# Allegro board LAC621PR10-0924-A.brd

Outline 306.3 x 113.1 mm; copper layers: TOP, GND1, IN1, GND2, IN2, IN3, VCC, IN4, GND3, BOTTOM. Coordinates in mm from the lower left corner of the outline.

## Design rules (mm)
net group 85H-SATA_3.9/5.3/4.3/4.3/5.3/3.9: nets SATA_LED SATA_LED#
net group CLK_ITPXDP-R: nets CLK_ITPXDP_N_R CLK_ITPXDP_P_R
net group CLK_PCIE_N1: nets CLK_PCIE_N1 CLK_PCIE_P1
net group CLK_PCIE_N2: nets CLK_PCIE_N2 CLK_PCIE_P2
net group CLK_PCIE_N3: nets CLK_PCIE_N3 CLK_PCIE_P3
net group CLK_PCIE_N4: nets CLK_PCIE_N4 CLK_PCIE_P4
net group CLK_PCIE_N5: nets CLK_PCIE_N5 CLK_PCIE_P5
net group CPU_DP1_N1: nets CPU_DP1_N1 CPU_DP1_P1
net group CPU_DP1_P0: nets CPU_DP1_N0 CPU_DP1_P0
net group CPU_DP1_P2: nets CPU_DP1_N2 CPU_DP1_P2
net group CPU_DP1_P3: nets CPU_DP1_N3 CPU_DP1_P3
net group CPU_DP2_N0: nets CPU_DP2_N0 CPU_DP2_P0
net group CPU_DP2_N0_C: nets CPU_DP2_N0_C CPU_DP2_P0_C
net group CPU_DP2_N1_C: nets CPU_DP2_N1_C CPU_DP2_P1_C
net group CPU_DP2_N2_C: nets CPU_DP2_N2_C CPU_DP2_P2_C
net group CPU_DP2_N3_C: nets CPU_DP2_N3_C CPU_DP2_P3_C
net group CPU_DP2_P1: nets CPU_DP2_N1 CPU_DP2_P1
net group CPU_DP2_P2: nets CPU_DP2_N2 CPU_DP2_P2
net group CPU_DP2_P3: nets CPU_DP2_N3 CPU_DP2_P3
net group CPU_DP3_AUXN: nets CPU_DP3_AUXN CPU_DP3_AUXP
net group CSS_1: nets CSSN_1 CSSP_1
net group CURRENT: nets DOCK_DCIN_IS+ DOCK_DCIN_IS-
net group DDRA-C-S10(11/10)/10(11/10)/19(20): nets DDR_A_CKE2 DDR_A_CKE3
net group DDRA-MA: nets DDR_A_MA7 DDR_A_MA10
net group DDRB-CTL: nets DDR_B_CKE2 DDR_B_CKE3
net group DIFFPAIR0: nets LPSS_UART2_RXD LPSS_UART2_TXD
net group DP2: nets SW1_DP0_AUXN_C SW1_DP0_AUXP_C
net group DP3_PCIE_PRX_C_DTX_11: nets PCIE_PRX_C_DTX_N11 PCIE_PRX_C_DTX_P11
net group DP3_PCIE_PRX_C_DTX_12: nets PCIE_PRX_C_DTX_N12 PCIE_PRX_C_DTX_P12
net group DP3_PCIE_PRX_C_RD_DTX_11: nets PCIE_PRX_C_RD_DTX_N11 PCIE_PRX_C_RD_DTX_P11
net group DP3_PCIE_PRX_C_RD_DTX_12: nets PCIE_PRX_C_RD_DTX_N12 PCIE_PRX_C_RD_DTX_P12
net group DP3_PCIE_PRX_DTX_11: nets PCIE_PRX_DTX_N11 PCIE_PRX_DTX_P11
net group DP3_PCIE_PRX_DTX_12: nets PCIE_PRX_DTX_N12 PCIE_PRX_DTX_P12
net group DP3_PCIE_PRX_RD_DTX_11: nets PCIE_PRX_RD_DTX_N11 PCIE_PRX_RD_DTX_P11
net group DP3_PCIE_PRX_RD_DTX_12: nets PCIE_PRX_RD_DTX_N12 PCIE_PRX_RD_DTX_P12
net group DP3_PCIE_PTX_C_DRX_11: nets PCIE_PTX_C_DRX_N11 PCIE_PTX_C_DRX_P11
net group DP3_PCIE_PTX_C_DRX_12: nets PCIE_PTX_C_DRX_N12 PCIE_PTX_C_DRX_P12
net group DP3_PCIE_PTX_C_RD_DRX_11: nets PCIE_PTX_C_RD_DRX_N11 PCIE_PTX_C_RD_DRX_P11
net group DP3_PCIE_PTX_C_RD_DRX_12: nets PCIE_PTX_C_RD_DRX_N12 PCIE_PTX_C_RD_DRX_P12
net group DP3_PCIE_PTX_DRX_11: nets PCIE_PTX_DRX_N11 PCIE_PTX_DRX_P11
net group DP3_PCIE_PTX_DRX_12: nets PCIE_PTX_DRX_N12 PCIE_PTX_DRX_P12
net group DP3_PCIE_PTX_RD_DRX_11: nets PCIE_PTX_RD_DRX_N11 PCIE_PTX_RD_DRX_P11
net group DP3_PCIE_PTX_RD_DRX_12: nets PCIE_PTX_RD_DRX_N12 PCIE_PTX_RD_DRX_P12
net group DP3_SATA_PRX_C_DTX_0: nets SATA_PRX_C_DTX_N0 SATA_PRX_C_DTX_P0
net group DP3_SATA_PRX_C_RD_DTX_0: nets SATA_PRX_C_RD_DTX_N0 SATA_PRX_C_RD_DTX_P0
net group DP3_SATA_PRX_DTX_0: nets SATA_PRX_DTX_N0 SATA_PRX_DTX_P0
net group DP3_SATA_PRX_RD_DTX_0: nets SATA_PRX_RD_DTX_N0 SATA_PRX_RD_DTX_P0
net group DP3_SATA_PTX_C_DRX_0: nets SATA_PTX_C_DRX_N0 SATA_PTX_C_DRX_P0
net group DP3_SATA_PTX_C_RD_DRX_0: nets SATA_PTX_C_RD_DRX_N0 SATA_PTX_C_RD_DRX_P0
net group DP3_SATA_PTX_DRX_0: nets SATA_PTX_DRX_N0 SATA_PTX_DRX_P0
net group DP3_SATA_PTX_RD_DRX_0: nets SATA_PTX_RD_DRX_N0 SATA_PTX_RD_DRX_P0
net group DP3_USB20_2_R: nets USB20_N2_R USB20_P2_R
net group DP4: nets VCC_GT_SENSE VSS_GT_SENSE
net group DP5: nets VCCIO_SENSE VSSIO_SENSE
net group DP6: nets VCCSENSE VSSSENSE
net group DP_HUB-DP0-0: nets HUB_DP0_N0 HUB_DP0_P0
net group DP_HUB-DP0-0-C: nets HUB_DP0_N0_C HUB_DP0_P0_C
net group DP_HUB-DP0-0-R: nets HUB_DP0_N0_R HUB_DP0_P0_R
net group DP_HUB-DP0-1: nets HUB_DP0_N1 HUB_DP0_P1
net group DP_HUB-DP0-1-C: nets HUB_DP0_N1_C HUB_DP0_P1_C
net group DP_HUB-DP0-1-R: nets HUB_DP0_N1_R HUB_DP0_P1_R
net group DP_HUB-DP0-2: nets HUB_DP0_N2 HUB_DP0_P2
net group DP_HUB-DP0-2-C: nets HUB_DP0_N2_C HUB_DP0_P2_C
net group DP_HUB-DP0-2-R: nets HUB_DP0_N2_R HUB_DP0_P2_R
net group DP_HUB-DP0-3: nets HUB_DP0_N3 HUB_DP0_P3
net group DP_HUB-DP0-3-C: nets HUB_DP0_N3_C HUB_DP0_P3_C
net group DP_HUB-DP0-3-R: nets HUB_DP0_N3_R HUB_DP0_P3_R
net group DP_HUB-DP1-0: nets HUB_DP1_N0 HUB_DP1_P0
net group DP_HUB-DP1-0-C: nets HUB_DP1_N0_C HUB_DP1_P0_C
net group DP_HUB-DP1-0-R: nets HUB_DP1_N0_R HUB_DP1_P0_R
net group DP_HUB-DP1-1: nets HUB_DP1_N1 HUB_DP1_P1
net group DP_HUB-DP1-1-C: nets HUB_DP1_N1_C HUB_DP1_P1_C
net group DP_HUB-DP1-1-R: nets HUB_DP1_N1_R HUB_DP1_P1_R
net group DP_HUB-DP1-2: nets HUB_DP1_N2 HUB_DP1_P2
net group DP_HUB-DP1-2-C: nets HUB_DP1_N2_C HUB_DP1_P2_C
net group DP_HUB-DP1-2-R: nets HUB_DP1_N2_R HUB_DP1_P2_R
net group DP_HUB-DP1-3: nets HUB_DP1_N3 HUB_DP1_P3
net group DP_HUB-DP1-3-C: nets HUB_DP1_N3_C HUB_DP1_P3_C
net group DP_HUB-DP1-3-R: nets HUB_DP1_N3_R HUB_DP1_P3_R
net group DP_SW1-DP1-0: nets SW1_DP1_N0 SW1_DP1_P0
net group DP_SW1-DP1-0-C: nets SW1_DP1_N0_C SW1_DP1_P0_C
net group DP_SW1-DP1-1: nets SW1_DP1_N1 SW1_DP1_P1
net group DP_SW1-DP1-1-C: nets SW1_DP1_N1_C SW1_DP1_P1_C
net group DP_SW1-DP1-2: nets SW1_DP1_N2 SW1_DP1_P2
net group DP_SW1-DP1-2-C: nets SW1_DP1_N2_C SW1_DP1_P2_C
net group DP_SW1-DP1-3: nets SW1_DP1_N3 SW1_DP1_P3
net group DP_SW1-DP1-3-C: nets SW1_DP1_N3_C SW1_DP1_P3_C
net group DP_SW1_DP0_0: nets SW1_DP0_N0 SW1_DP0_P0
net group DP_SW1_DP0_0_C: nets SW1_DP0_N0_C SW1_DP0_P0_C
net group DP_SW1_DP0_1: nets SW1_DP0_N1 SW1_DP0_P1
net group DP_SW1_DP0_1_C: nets SW1_DP0_N1_C SW1_DP0_P1_C
net group DP_SW1_DP0_2: nets SW1_DP0_N2 SW1_DP0_P2
net group DP_SW1_DP0_2_C: nets SW1_DP0_N2_C SW1_DP0_P2_C
net group DP_SW1_DP0_3: nets SW1_DP0_N3 SW1_DP0_P3
net group DP_SW1_DP0_3_C: nets SW1_DP0_N3_C SW1_DP0_P3_C
net group HUB_DP0_AUX-C: nets HUB_DP0_AUXN_C HUB_DP0_AUXP_C
net group HUB_DP1_AUX-C: nets HUB_DP1_AUXN_C HUB_DP1_AUXP_C
net group PCIE_PRX_C_DTX_N9: nets PCIE_PRX_C_DTX_N9 PCIE_PRX_C_DTX_P9
net group PCIE_PRX_C_DTX_N10: nets PCIE_PRX_C_DTX_N10 PCIE_PRX_C_DTX_P10
net group PCIE_PRX_DTX_N5: nets PCIE_PRX_DTX_N5 PCIE_PRX_DTX_P5
net group PCIE_PRX_DTX_N6: nets PCIE_PRX_DTX_N6 PCIE_PRX_DTX_P6
net group PCIE_PRX_DTX_N9: nets PCIE_PRX_DTX_N9 PCIE_PRX_DTX_P9
net group PCIE_PRX_DTX_N10: nets PCIE_PRX_DTX_N10 PCIE_PRX_DTX_P10
net group PCIE_PTX_C_DRX_N5: nets PCIE_PTX_C_DRX_N5 PCIE_PTX_C_DRX_P5
net group PCIE_PTX_C_DRX_N6: nets PCIE_PTX_C_DRX_N6 PCIE_PTX_C_DRX_P6
net group PCIE_PTX_C_DRX_N9: nets PCIE_PTX_C_DRX_N9 PCIE_PTX_C_DRX_P9
net group PCIE_PTX_C_DRX_N10: nets PCIE_PTX_C_DRX_N10 PCIE_PTX_C_DRX_P10
net group PCIE_PTX_DRX_N5: nets PCIE_PTX_DRX_N5 PCIE_PTX_DRX_P5
net group PCIE_PTX_DRX_N6: nets PCIE_PTX_DRX_N6 PCIE_PTX_DRX_P6
net group PCIE_PTX_DRX_N9: nets PCIE_PTX_DRX_N9 PCIE_PTX_DRX_P9
net group PCIE_PTX_DRX_N10: nets PCIE_PTX_DRX_N10 PCIE_PTX_DRX_P10
net group PECI-SINGLE: nets PECI_EC PECI_EC_R
net group REM_DIODE1_: nets REM_DIODE1_N REM_DIODE1_P
net group REM_DIODE2_: nets REM_DIODE2_N REM_DIODE2_P
net group REM_DIODE4_: nets REM_DIODE4_N REM_DIODE4_P
net group RJ45_MDIN0: nets RJ45_MDIN0 RJ45_MDIP0
net group RJ45_MDIN1: nets RJ45_MDIN1 RJ45_MDIP1
net group RJ45_MDIN2: nets RJ45_MDIN2 RJ45_MDIP2
net group RJ45_MDIN3: nets RJ45_MDIN3 RJ45_MDIP3
net group SATA_PRX_C_DTX_N1: nets SATA_PRX_C_DTX_N1 SATA_PRX_C_DTX_P1
net group SATA_PRX_DTX_N1: nets SATA_PRX_DTX_N1 SATA_PRX_DTX_P1
net group SATA_PTX_C_DRX_N1: nets SATA_PTX_C_DRX_N1 SATA_PTX_C_DRX_P1
net group SATA_PTX_DRX_N1: nets SATA_PTX_DRX_N1 SATA_PTX_DRX_P1
net group SD/MMCDAT0/RCLK+: nets SD/MMCDAT0/RCLK+ SD/MMCDAT1/RCLK-
net group SD/MMCDAT-RCLKR: nets SD/MMCDAT0/RCLK+_R SD/MMCDAT1/RCLK-_R
net group SW1_DP1_AUX-C: nets SW1_DP1_AUXN_C SW1_DP1_AUXP_C
net group USB3_PRX_DTX_N3: nets USB3_PRX_DTX_N3 USB3_PRX_DTX_P3
net group USB3_PRX_DTX_N4: nets USB3_PRX_DTX_N4 USB3_PRX_DTX_P4
net group USB3_PRX_DTX_P1: nets USB3_PRX_DTX_N1 USB3_PRX_DTX_P1
net group USB3_PRX_DTX_P2: nets USB3_PRX_DTX_N2 USB3_PRX_DTX_P2
net group USB3_PRX_L_DTX_N1: nets USB3_PRX_L_DTX_N1 USB3_PRX_L_DTX_P1
net group USB3_PRX_L_DTX_N3: nets USB3_PRX_L_DTX_N3 USB3_PRX_L_DTX_P3
net group USB3_PTX_C_DRX_N1: nets USB3_PTX_C_DRX_N1 USB3_PTX_C_DRX_P1
net group USB3_PTX_C_DRX_N3: nets USB3_PTX_C_DRX_N3 USB3_PTX_C_DRX_P3
net group USB3_PTX_DRX_N1: nets USB3_PTX_DRX_N1 USB3_PTX_DRX_P1
net group USB3_PTX_DRX_N2: nets USB3_PTX_DRX_N2 USB3_PTX_DRX_P2
net group USB3_PTX_DRX_N3: nets USB3_PTX_DRX_N3 USB3_PTX_DRX_P3
net group USB3_PTX_DRX_N4: nets USB3_PTX_DRX_N4 USB3_PTX_DRX_P4
net group USB3_PTX_L_DRX_N1: nets USB3_PTX_L_DRX_N1 USB3_PTX_L_DRX_P1
net group USB3_PTX_L_DRX_N3: nets USB3_PTX_L_DRX_N3 USB3_PTX_L_DRX_P3
net group VSA_SEN: nets VSA_SEN+ VSA_SEN-
net group ASYNCHRONOUS: nets +DDR_VREF_A_CA +DDR_VREF_B_DQ CFG_RCOMP CPU_POPIRCOMP DDR_DRAMRST# DDR_DRAMRST#_R EDP_COMP EDRAM_OPIO_RCOMP EMMC_RCOMP EOPIO_RCOMP H_CATERR# H_PROCHOT# H_PROCHOT#_R H_PROCHOT#_R1 H_THERMTRIP# PCH_PLTRST# PCH_PLTRST#_EC PCH_POPIRCOMP PCIE_RCOMPN PCIE_RCOMPP PLTRST_5048# PLTRST_LAN# PLTRST_TPM# PLTRST_VMM2320# SD_RCOMP SM_RCOMP0 SM_RCOMP1 SM_RCOMP2 THERMATRIP2# THERMATRIP3# USBCOMP VCCST_PWRGD XDP_OBS0 XDP_OBS0_R XDP_OBS1 XDP_OBS1_R XDP_OBS2_R XDP_OBS3_R
net group BC: nets BC_CLK_ECE1117 BC_CLK_ECE5048 BC_DAT_ECE1117 BC_DAT_ECE5048
net group CARD READER: nets SD/MMCCD# SD/MMCCLK SD/MMCCLK_R SD/MMCCMD SD/MMCDAT2 SD/MMCDAT2_R SD/MMCDAT3 SD/MMCDAT3_R SDWP
net group CL_IAMT: nets PCH_CL_CLK1 PCH_CL_DATA1 PCH_CL_RST1#
net group CLK: nets CLK_27M_IN CLK_27M_OUT CLK_27M_OUT_R CLK_PCI_DOCK CLK_PCI_LPDEBUG CLK_PCI_MEC CLKDET# CLKREQ_PCIE#0 CLKREQ_PCIE#1 CLKREQ_PCIE#2 CLKREQ_PCIE#3 CLKREQ_PCIE#4 CLKREQ_PCIE#5 CPU_XDP_TCLK DAI_12MHZ# DAI_BCLK# DMIC_CLK0 DMIC_CLK_CODEC HDA_BIT_CLK HDA_BIT_CLK_R HUB_SPI_CLK I2S_MCLK JTAG_CLK MEC_XTAL1 MEC_XTAL2 MEC_XTAL2_R MSCLK PCH_JTAG_TCK PCI_CLK_LPC0 PCI_CLK_LPC1 XCLK_BIASREF XTAL24_IN XTAL24_OUT XTAL24_OUT_R XTALI XTALO XTALO_R
net group CLK-DF: nets CLK_ITPXDP_N CLK_ITPXDP_P CLK_PCIE_N0 CLK_PCIE_P0
net group CODEC: nets AUD_HP_NB_SENSE AUD_SENSE_A AUD_SENSE_B RING2 RING2_R SLEEVE SLEEVE_R
net group CRITICAL: nets H_VCCST_PWRGD_XDP INTRUDER# PCH_DPWROK PCH_PCIE_WAKE# PCH_RSMRST# PCH_RSMRST#_Q PCIE_WAKE# PCIE_WAKE#_R RESET_OUT# RESET_OUT#_R SIO_PWRBTN# SIO_RCIN#
net group CRITICAL SIGNALS: nets H_CPUPWRGD SIO_SLP_A# XDP_DBRESET#
net group CRT: nets HUB_VGA_BLUE HUB_VGA_GREEN HUB_VGA_HSYNC HUB_VGA_RED HUB_VGA_VSYNC SW2_VGA1_BLUE SW2_VGA1_GREEN SW2_VGA1_HSYNC SW2_VGA1_RED SW2_VGA1_VSYNC SW2_VGA2_BLUE SW2_VGA2_GREEN SW2_VGA2_HSYNC SW2_VGA2_RED SW2_VGA2_VSYNC VGA1_BLUE_L VGA1_GREEN_L VGA1_HSYNC_L VGA1_RED_L VGA1_VSYNC_L
net group DDR: nets DDR_A_CKE0 DDR_A_CKE1 DDR_A_CLK0 DDR_A_CLK1 DDR_A_CLK#0 DDR_A_CLK#1 DDR_A_CS#0 DDR_A_CS#1 DDR_A_D0 DDR_A_D1 DDR_A_D2 DDR_A_D3 DDR_A_D4 DDR_A_D5 DDR_A_D6 DDR_A_D7 DDR_A_D8 DDR_A_D9 DDR_A_D10 DDR_A_D11 DDR_A_D12 DDR_A_D13 DDR_A_D14 DDR_A_D15 DDR_A_D16 DDR_A_D17 DDR_A_D18 DDR_A_D19 DDR_A_D20 DDR_A_D21 DDR_A_D22 DDR_A_D23 DDR_A_D24 DDR_A_D25 DDR_A_D26 DDR_A_D27 DDR_A_D28 DDR_A_D29 DDR_A_D30 DDR_A_D31 DDR_A_D32 DDR_A_D33 DDR_A_D34 DDR_A_D35 DDR_A_D36 DDR_A_D37 DDR_A_D38 DDR_A_D39 DDR_A_D40 DDR_A_D41 DDR_A_D42 DDR_A_D43 DDR_A_D44 DDR_A_D45 DDR_A_D46 DDR_A_D47 DDR_A_D48 DDR_A_D49 DDR_A_D50 DDR_A_D51 DDR_A_D52 DDR_A_D53 DDR_A_D54 DDR_A_D55 DDR_A_D56 DDR_A_D57 DDR_A_D58 DDR_A_D59 DDR_A_D60 DDR_A_D61 DDR_A_D62 DDR_A_D63 DDR_A_DQS0 DDR_A_DQS1 DDR_A_DQS2 DDR_A_DQS3 DDR_A_DQS4 DDR_A_DQS5 DDR_A_DQS6 DDR_A_DQS7 DDR_A_DQS#0 DDR_A_DQS#1 DDR_A_DQS#2 DDR_A_DQS#3 DDR_A_DQS#4 DDR_A_DQS#5 DDR_A_DQS#6 DDR_A_DQS#7 DDR_A_MA0 DDR_A_MA1 DDR_A_MA2 DDR_A_MA3 DDR_A_MA4 DDR_A_MA5 DDR_A_MA6 DDR_A_MA8 DDR_A_MA9 DDR_A_MA11 DDR_A_MA12 DDR_A_MA13 DDR_A_MA14 DDR_A_MA15 DDR_A_ODT0 DDR_A_ODT1 DDR_B_CKE0 DDR_B_CKE1 DDR_B_CLK0 DDR_B_CLK1 DDR_B_CLK#0 DDR_B_CLK#1 DDR_B_CS#0 DDR_B_CS#1 DDR_B_D0 DDR_B_D1 DDR_B_D2 DDR_B_D3 DDR_B_D4 DDR_B_D5 DDR_B_D6 DDR_B_D7 DDR_B_D8 DDR_B_D9 DDR_B_D10 DDR_B_D11 DDR_B_D12 DDR_B_D13 DDR_B_D14 DDR_B_D15 DDR_B_D16 DDR_B_D17 DDR_B_D18 DDR_B_D19 DDR_B_D20 DDR_B_D21 DDR_B_D22 DDR_B_D23 DDR_B_D24 DDR_B_D25 DDR_B_D26 DDR_B_D27 DDR_B_D28 DDR_B_D29 DDR_B_D30 DDR_B_D31 DDR_B_D32 DDR_B_D33 DDR_B_D34 DDR_B_D35 DDR_B_D36 DDR_B_D37 DDR_B_D38 DDR_B_D39 DDR_B_D40 DDR_B_D41 DDR_B_D42 DDR_B_D43 DDR_B_D44 DDR_B_D45 DDR_B_D46 DDR_B_D47 DDR_B_D48 DDR_B_D49 DDR_B_D50 DDR_B_D51 DDR_B_D52 DDR_B_D53 DDR_B_D54 DDR_B_D55 DDR_B_D56 DDR_B_D57 DDR_B_D58 DDR_B_D59 DDR_B_D60 DDR_B_D61 DDR_B_D62 DDR_B_D63 DDR_B_DQS0 DDR_B_DQS1 DDR_B_DQS2 DDR_B_DQS3 DDR_B_DQS4 DDR_B_DQS5 DDR_B_DQS6 DDR_B_DQS7 DDR_B_DQS#0 DDR_B_DQS#1 DDR_B_DQS#2 DDR_B_DQS#3 DDR_B_DQS#4 DDR_B_DQS#5 DDR_B_DQS#6 DDR_B_DQS#7 DDR_B_MA0 DDR_B_MA1 DDR_B_MA2 DDR_B_MA3 DDR_B_MA4 DDR_B_MA5 DDR_B_MA6 DDR_B_MA7 DDR_B_MA8 DDR_B_MA9 DDR_B_MA10 DDR_B_MA11 DDR_B_MA13 DDR_B_MA14 DDR_B_MA15 DDR_B_ODT0 DDR_B_ODT1
net group DDRA-MA-S10(11/10)/10(11/10)/19(20): nets DDR_A_ACT# DDR_A_BA0 DDR_A_BA1 DDR_A_BG0 DDR_A_BG1 DDR_A_MA16 DDR_A_PARITY
net group DDRB-MA: nets DDR_B_MA12
net group DDRB-MA-S10(11/10)/10(11/10)/19(20): nets DDR_B_ACT# DDR_B_BA0 DDR_B_BA1 DDR_B_BG0 DDR_B_BG1 DDR_B_MA16 DDR_B_PARITY
net group DP: nets CPU_DP2_AUXN CPU_DP2_AUXN_C CPU_DP2_AUXP CPU_DP2_AUXP_C HUB_DP0_AUXN HUB_DP0_AUXP HUB_DP1_AUXN HUB_DP1_AUXP HUB_DP1_SCL HUB_DP1_SDA HUB_SW1_AUXN HUB_SW1_AUXP HUB_SW2_AUXN HUB_SW2_AUXP SW1_DP0_AUXN SW1_DP0_AUXP SW1_DP1_AUXN SW1_DP1_AUXP
net group DP_3.9/3.7/4.3/4.3/3.7/3.9: nets CPU_DP2_HPD
net group EDP: nets EDP_AUXN EDP_AUXN_C EDP_AUXP EDP_AUXP_C EDP_TXN0 EDP_TXN0_C EDP_TXN1 EDP_TXN1_C EDP_TXP0 EDP_TXP0_C EDP_TXP1 EDP_TXP1_C
net group EMI: nets BIA_PWM BIA_PWM_EC BST_3V BST_5V CLKRUN# DAI_LRCK# EC5048_TX EDP_BIA_PWM HOST_DEBUG_TX I2S_BCLK M_ID2# TP_LAN_JTAG_TCK
net group ESD-GND: nets CPU_XDP_PRDY# CPU_XDP_PREQ# CPU_XDP_TDI CPU_XDP_TDO CPU_XDP_TMS CPU_XDP_TRST# PCH_JTAG_TDI PCH_JTAG_TDO PCH_JTAG_TMS POWER_SW#_MB POWER_SW_IN# RUNPWROK
net group ESD-NOCROSS-MOAT: nets CFG0 CFG1 CFG2 CFG3 CFG4 CFG5 CFG6 CFG7 CFG8 CFG9 CFG10 CFG11 CFG12 CFG13 CFG14 CFG15 CFG16 CFG17 CFG18 CFG19 SIO_EXT_SMI#
net group HDA: nets HDA_RST# HDA_RST#_R HDA_SDIN0 HDA_SDIN0_R HDA_SDOUT HDA_SDOUT_R HDA_SYNC HDA_SYNC_R
net group HDMI: nets CPU_DP1_AUXN CPU_DP1_AUXP HDMI_CLKN HDMI_CLKP HDMI_L_CLKN HDMI_L_CLKP HDMI_L_TX_N0 HDMI_L_TX_N1 HDMI_L_TX_N2 HDMI_L_TX_P0 HDMI_L_TX_P1 HDMI_L_TX_P2 HDMI_TX_N0 HDMI_TX_N1 HDMI_TX_N2 HDMI_TX_P0 HDMI_TX_P1 HDMI_TX_P2
net group HP: nets AUD_HP_OUT_L AUD_HP_OUT_L1 AUD_HP_OUT_R AUD_HP_OUT_R1 AUD_OUT_L AUD_OUT_R
net group I2C: nets I2C_1_SCL I2C_1_SDA I2C_HUB_SCL I2C_HUB_SDA ISH_I2C2_SCL ISH_I2C2_SCL_R ISH_I2C2_SDA ISH_I2C2_SDA_R
net group MDI: nets LAN_MDIN0 LAN_MDIN0_L LAN_MDIN1 LAN_MDIN1_L LAN_MDIN2 LAN_MDIN2_L LAN_MDIN3 LAN_MDIN3_L LAN_MDIP0 LAN_MDIP0_L LAN_MDIP1 LAN_MDIP1_L LAN_MDIP2 LAN_MDIP2_L LAN_MDIP3 LAN_MDIP3_L SW_LAN0_MDIN0 SW_LAN0_MDIN1 SW_LAN0_MDIN2 SW_LAN0_MDIN3 SW_LAN0_MDIP0 SW_LAN0_MDIP1 SW_LAN0_MDIP2 SW_LAN0_MDIP3 SW_LAN1_MDIN0 SW_LAN1_MDIN1 SW_LAN1_MDIN2 SW_LAN1_MDIN3 SW_LAN1_MDIP0 SW_LAN1_MDIP1 SW_LAN1_MDIP2 SW_LAN1_MDIP3
net group OTHER-SINGLE: nets BAT1_LED# BAT2_LED# BATT_WHITE# BATT_YELLOW#
net group PCIE: nets PCIE_PRX_DTX_N3 PCIE_PRX_DTX_P3 PCIE_PTX_C_DRX_N3 PCIE_PTX_C_DRX_P3 PCIE_PTX_DRX_N3 PCIE_PTX_DRX_P3
net group POWER-20: nets +1.0V_PRIM_COREP +1.0V_VCCST_C +1.0V_VCCSTG_C +1.0V_VCCSTG_R +1.5V_VIN +1.8VALWP +1VALWP +1VALWP_B+ +1VS_VCCIOP +3.3V_RUN_AUDIO_UZ5 +DV33_18 +REGCTL_PNP10 +SDREG2 +SIM_PWR CHAGER_SRC GPU_B+
net group POWERS: nets +1.0V_AMPHYPLL +1.0V_APLLEBB +1.0V_CLK1 +1.0V_CLK2 +1.0V_CLK3 +1.0V_CLK4 +1.0V_CLK5 +1.0V_CLK6 +1.0V_DTS +1.0V_MPHYAON +1.0V_PRIM_CORE +1.0V_PRIM_XDP +1.0V_RUN_VMM +1.0V_SRAM +1.0V_VCCST +1.0V_VCCSTG +1.0V_VMM_VDD +1.0V_VMM_VDDTX +1.0VO_DSW +1.0VS_VCCIO +1.5V_RUN +1.5V_RUN_AUDIO +3.3V_1.8V_PGPPA +3.3V_1.8V_PGPPG +3.3V_ALW_DSW +3.3V_LAN_UZ2 +3.3V_M_TPM +3.3V_M_UZ8 +3.3V_MMI_AUX +3.3V_MMI_IN +3.3V_PGPPD +3.3V_PGPPE +3.3V_RUN_UZ3 +3.3V_WLAN_UZ3 +3.3V_WWAN +5V_RUN_PVDD +EDP_VDD +USB_REAR_PWR +VCC_GTUS
net group PWR: nets +0.9V_LAN +1.2V_LDO +1.8V_RUN_CARD +3.3V_ALW2 +3.3V_ALW_PCH +3.3V_ALW_UE1 +3.3V_ALW_UE2 +3.3V_ALWP +3.3V_CAM +3.3V_HDD +3.3V_LAN +3.3V_LAN_OUT +3.3V_M +3.3V_RTC_LDO +3.3V_RUN_AUDIO +3.3V_RUN_CARD +3.3V_RUN_VDDA +3.3V_RUN_VDDIO +3.3V_RUN_VMM +3.3V_SPI +3.3V_TP +3.3V_WLAN +5V_ALW2 +5V_ALWP +5V_HDD +5V_RUN +5V_RUN_AUDIO +5V_USB_CHG_PWR +BL_PWR_SRC +CAP_LDO +COINCELL +CRT_VCC +DC_IN +DC_IN_SS +DCIN +DCIN_JACK +GND_CHASSIS +LCDVDD +LOM_VCT +MIC1_VREF_OUT +NBDOCK_DC_IN_SS +PBATT +PECI_VREF +RSVD_VCC3P3_1 +RTC_CELL +RTC_CELL_VBAT +SDC_IN +USB_LEFT_PWR +V_DDR_REF +VCHGR +VDDA_AVDD1 +VDDA_PVDD +VHDMI_VCC +VR_CAP +VREFOUT
net group RTC: nets PCH_RTCRST# PCH_RTCX1 PCH_RTCX2 PCH_RTCX2_R SRTCRST# SUSCLK SUSCLK_R WIGIG_32KHZ
net group S-20/20: nets +DDR_VREF_CA
net group SD: nets SD_UHS2_D0N SD_UHS2_D0P SD_UHS2_D1N SD_UHS2_D1P
net group SD-NOCROSS-MOAT: nets DOCK_POR_RST# JTAG_RST# ME_SUS_PWR_ACK SUSACK# USB_OC0# USB_OC1# USB_OC2#
net group SIM: nets UIM_CLK UIM_DATA UIM_RESET
net group SM: nets CHARGER_SMBCLK CHARGER_SMBDAT CLK_KBD CLK_MSE CLK_TP_SIO CPU_DP1_CTRL_CLK CPU_DP1_CTRL_DATA CPU_DP2_CTRL_CLK CPU_DP2_CTRL_DATA DAT_KBD DAT_MSE DAT_TP_SIO DDR_XDP_WAN_SMBCLK DDR_XDP_WAN_SMBDAT DOCK_SMB_CLK DOCK_SMB_DAT HUB_DP0_SCL HUB_DP0_SDA HUB_VGA_SCL HUB_VGA_SDA MEM_SMBCLK MEM_SMBDATA PBAT_SMBCLK PBAT_SMBCLK_C PBAT_SMBDAT PBAT_SMBDAT_C SML0_SMBCLK SML0_SMBDATA SML1_SMBCLK SML1_SMBDATA SW2_VGA1_SCL SW2_VGA1_SDA SW2_VGA2_SCL SW2_VGA2_SDA USH_SMBCLK USH_SMBDAT
net group SMB: nets GPU_SMBCLK
net group SMB-5: nets GPU_SMBDAT
net group SPI: nets CLK_PCI_5048 PCH_SPI_CLK PCH_SPI_CLK_0_R PCH_SPI_CLK_1_R PCH_SPI_CLK_2_R PCH_SPI_CLK_R1 PCH_SPI_CS#0 PCH_SPI_CS#0_R1 PCH_SPI_CS#0_R2 PCH_SPI_CS#1 PCH_SPI_CS#1_R1 PCH_SPI_CS#1_R2 PCH_SPI_CS#2 PCH_SPI_CS#2_R PCH_SPI_D0 PCH_SPI_D0_0_R PCH_SPI_D0_1_R PCH_SPI_D0_2_R PCH_SPI_D0_R1 PCH_SPI_D1 PCH_SPI_D1_0_R PCH_SPI_D1_1_R PCH_SPI_D1_2_R PCH_SPI_D1_R1 PCH_SPI_D2 PCH_SPI_D2_0_R PCH_SPI_D2_1_R PCH_SPI_D2_R1 PCH_SPI_D3 PCH_SPI_D3_0_R PCH_SPI_D3_1_R PCH_SPI_D3_R1 PCH_SPI_DO2_XDP PCH_SPI_DO_XDP
net group SPK: nets INT_SPK_L+ INT_SPK_L- INT_SPK_R+ INT_SPK_R- INT_SPKR_L+ INT_SPKR_L- INT_SPKR_R+ INT_SPKR_R-
net group SVID: nets H_CPU_SVIDALRT# VIDALERT_N VIDSCLK VIDSOUT
net group USB2.0: nets USB20_N4_R USB20_N9_R USB20_P4_R USB20_P9_R
net group USB3.0: nets USB3_PRX_DTX_N5 USB3_PRX_DTX_P5 USB3_PRX_L_DTX_N4 USB3_PRX_L_DTX_P4 USB3_PTX_C_DRX_N4 USB3_PTX_C_DRX_P4 USB3_PTX_DRX_N5 USB3_PTX_DRX_P5 USB3_PTX_L_DRX_N4 USB3_PTX_L_DRX_P4
net group USB3.0-DF12/12: nets USB3_PRX_L_DTX_N5 USB3_PRX_L_DTX_P5 USB3_PTX_C_DRX_N5 USB3_PTX_C_DRX_P5 USB3_PTX_L_DRX_N5 USB3_PTX_L_DRX_P5
net group USB20: nets SW_USB20_N1 SW_USB20_P1 USB20_N1 USB20_N1_R USB20_N2 USB20_N3 USB20_N3_R USB20_N4 USB20_N5 USB20_N6 USB20_N7 USB20_N8 USB20_N9 USB20_N10 USB20_P1 USB20_P1_R USB20_P2 USB20_P3 USB20_P3_R USB20_P4 USB20_P5 USB20_P6 USB20_P7 USB20_P8 USB20_P9 USB20_P10

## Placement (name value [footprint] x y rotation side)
C33  -  [C_0805]  131.53 95.75 270 bottom
C42  -  [C_0402]  156.04 108.11 270 top
C43  -  [C_0402]  154.27 107.19 90 top
C263  -  [C_0402]  285.42 83.74 180 bottom
C294  -  [C_0402]  135.98 106.81 90 top
C295  -  [C_0402]  138.26 93.76 270 bottom
C296  -  [C_0402]  136.87 106.81 90 top
C297  -  [C_0402]  139.28 93.76 270 bottom
C298  -  [C_0402]  137.76 106.81 90 top
C299  -  [C_0402]  140.17 93.76 270 bottom
C300  -  [C_0402]  143.09 93.76 270 bottom
C301  -  [C_0402]  143.98 93.76 270 bottom
C302  -  [C_0402]  137.37 93.76 270 bottom
C303  -  [C_0402]  138.64 106.81 90 top
C304  -  [C_0402]  141.18 93.76 270 bottom
C305  -  [C_0402]  139.53 106.81 90 top
C306  -  [C_0402]  142.07 93.76 270 bottom
C307  -  [C_0402]  140.42 106.81 90 top
C308  -  [C_0402]  141.31 106.81 90 top
C309  -  [C_0402]  142.2 106.81 90 top
C310  -  [C_0402]  146.54 95.89 270 bottom
C311  -  [C_0402]  143.5 109.38 0 top
C312  -  [C_0402]  148.68 102.9 90 top
C313  -  [C_0402]  149.57 102.9 90 top
C314  -  [C_0402]  150.46 103.81 270 top
C315  -  [C_0402]  151.34 103.81 270 top
C316  -  [C_0402]  164.98 109.43 0 top
C317  -  [C_0603]  130.06 95.83 270 bottom
C318  -  [C_0603]  179.03 101.81 270 top
C319  -  [C_0402]  165.11 101.04 0 top
CA1  -  [C_0402]  291.43 34.88 270 top
CA2  -  [C_0402]  290.84 36.91 0 top
CA3  -  [C_0402]  290.84 38.43 0 top
CA4  -  [C_0402]  291.96 32.27 270 top
CA5  -  [C_0402]  93.1 86.92 270 top
CA6  -  [C_0402]  93.99 86.92 270 top
CA7  -  [C_0201]  91.89 86.35 270 top
CA8  -  [C_0201]  284.91 31.7 0 top
CA9  -  [C_0603]  284.3 30.81 0 top
CA10  -  [C_0603]  273.8 33.99 180 top
CA11  -  [C_0201]  274.4 31.1 270 top
CA12  -  [C_0402]  294.7 35.61 0 top
CA13  -  [C_0402]  295.62 34.24 180 top
CA16  -  [C_0603]  283.93 39.07 90 top
CA17  -  [C_0201]  286.82 38.94 0 top
CA18  -  [C_0603]  286.41 39.83 0 top
CA19  -  [C_0402]  277.3 39.63 90 top
CA22  -  [C_0402]  279.97 39.65 90 top
CA23  -  [C_0402]  279.08 39.65 90 top
CA24  -  [C_0402]  278.19 39.63 90 top
CA25  -  [C_0603]  284.38 32.85 0 top
CA26  -  [C_0603]  285.33 28.66 270 top
CA27  -  [C_0402]  273.32 28.28 0 top
CA28  -  [C_0402]  273.32 27.39 0 top
CA29  -  [C_0603]  285.77 37.16 180 top
CA31  -  [C_0603]  273.77 38.05 180 top
CA33  -  [C_0402]  271.18 32.47 180 top
CA35  -  [C_0402]  285.53 29.67 180 top
CA41  -  [C_0402]  270.6 26.57 270 top
CA43  -  [C_0603]  280.5 27.83 270 top
CA44  -  [C_0603]  281.77 27.83 270 top
CA45  -  [C_0201]  281.27 39.32 0 top
CA46  -  [C_0603]  280.88 40.34 0 top
CA47  -  [C_0201]  276.57 39.64 90 top
CA48  -  [C_0603]  275.68 39.89 90 top
CA49  -  [C_0603]  285.77 35.89 180 top
CA50  -  [C_0201]  273.34 34.88 180 top
CA51  -  [C_0603]  283.04 27.83 270 top
CA52  -  [C_0603]  285.2 39.07 90 top
CA53  -  [C_0603]  273.46 31.83 180 top
CA54  -  [C_0402]  271.44 34.7 270 top
CC3  -  [C_0402]  178.7 41.1 90 top
CC4  -  [C_0402]  175.98 41.1 90 top
CC5  -  [C_0402]  179.79 42.9 90 top
CC6  -  [C_0402]  181.7 42.8 90 top
CC7  -  [C_0402]  192.11 55.76 90 top
CC8  -  [C_0402]  194.04 65.23 0 top
CC9  -  [C_0201]  189.83 68.57 270 bottom
CC10  -  [C_0201]  189.85 54.32 90 bottom
CC21  -  [C_0402]  152.49 83.09 180 bottom
CC22  -  [C_0402]  155.31 83.06 180 bottom
CC23  -  [C_0402]  181.24 61.28 90 bottom
CC24  -  [C_0402]  187.41 45.34 90 top
CC25  -  [C_0402]  260.95 25.78 90 bottom
CC26  -  [C_0402]  181.24 59.88 270 bottom
CC27  -  [C_0402]  161.73 43.64 270 top
CC28  -  [C_0201]  89.24 39.96 180 top
CC29  -  [C_0201]  77.18 86.15 90 top
CC30  -  [C_0201]  98.3 40.06 180 top
CC32  -  [C_0402]  90.66 49 0 bottom
CC33  -  [C_0402]  92.54 39.83 0 top
CC174  -  [C_0402]  156.86 43.04 180 top
CC175  -  [C_0402]  153.96 45.34 0 top
CC176  -  [C_0402]  153.96 44.45 0 top
CC177  -  [C_0402]  147.23 44.02 180 top
CC178  -  [C_0402]  156.98 44.96 0 top
CC179  -  [C_0402]  147.23 44.91 180 top
CC181  -  [C_0402]  156.37 61.17 180 top
CC182  -  [C_0402]  157.19 61.19 0 top
CC185  -  [C_0402]  148.45 61.24 180 top
CC186  -  [C_0402]  149.57 61.29 90 top
CC194  -  [C_0402]  150.41 62.21 0 top
CC195  -  [C_0402]  162.44 83.52 0 bottom
CC199  -  [C_0402]  162.29 85.4 0 top
CC202  -  [C_0402]  160.13 69.98 270 top
CC203  -  [C_0402]  164.61 72.29 0 top
CC204  -  [C_0402]  168.01 61.26 180 top
CC206  -  [C_0402]  160.59 66.12 90 top
CC208  -  [C_0402]  163.75 68.61 180 top
CC209  -  [C_0402]  162.37 67.16 180 top
CC210  -  [C_0805]  171.88 84.54 180 bottom
CC211  -  [C_0402]  164.86 70.37 0 top
CC212  -  [C_0402]  178.2 65.37 0 bottom
CC213  -  [C_0402]  166.97 45.42 180 top
CC214  -  [C_0201]  174.84 46.31 270 top
CC215  -  [C_0402]  160.05 63.81 180 top
CC216  -  [C_0402]  170.7 82.26 90 bottom
CC217  -  [C_0402]  159.96 64.72 180 top
CC218  -  [C_0402]  162 68.61 180 top
CC219  -  [C_0805]  166.08 82.35 90 bottom
CC220  -  [C_0805]  161.14 82.76 180 bottom
CC221  -  [C_0805]  157.69 85.36 90 bottom
CC222  -  [C_0402]  178.93 63.59 0 bottom
CC223  -  [C_0201]  163.52 61.67 90 top
CC224  -  [C_0402]  162.93 63.02 90 top
CC225  -  [C_0805]  190.13 64.89 90 bottom
CC226  -  [C_0805]  157.57 82.54 90 bottom
CC248  -  [C_0402]  148.47 62.11 180 top
CC249  -  [C_0402]  148.4 63 180 top
CC250  -  [C_0402]  157.19 62.08 0 top
CC251  -  [C_0402]  156.37 62.08 180 top
CC252  -  [C_0402]  157.03 64.32 0 top
CC253  -  [C_0402]  157.03 63.43 0 top
CC254  -  [C_0402]  145.45 61.32 90 top
CC255  -  [C_0402]  153.71 61.42 0 top
CC256  -  [C_0402]  153.71 60.53 0 top
CC257  -  [C_0402]  146.34 61.32 90 top
CC264  -  [C_0402]  166.42 71.43 90 top
CC266  -  [C_0402]  176.62 39.68 0 top
CC269  -  [C_0402]  87.49 39.81 270 top
CC270  -  [C_0201]  162.93 61.74 90 top
CC271  -  [C_0805]  170.27 93.93 0 bottom
CC272  -  [C_0805]  190.13 63.67 270 bottom
CC273  -  [C_0805]  198.8 59.77 180 bottom
CC274  -  [C_0805]  197.53 62.69 180 bottom
CC279  -  [C_0603]  180.17 61.51 90 top
CC280  -  [C_0603]  178.95 61.51 90 top
CC281  -  [C_0201]  166.4 69.26 0 top
CC282  -  [C_0603]  153.87 63.07 180 top
CC283  -  [C_0603]  167.24 90.53 90 top
CC284  -  [C_0603]  165.97 90.53 90 top
CC285  -  [C_0603]  169.3 90.93 90 top
CC286  -  [C_0603]  209.22 50.68 270 top
CC287  -  [C_0603]  121.23 71.02 0 top
CC288  -  [C_0402]  160.04 62.93 180 top
CC294  -  [C_0603]  153.64 43.39 0 top
CC295  -  [C_0603]  153.64 42.12 0 top
CC296  -  [C_0603]  147.28 42.88 180 top
CC297  -  [C_0402]  150.41 61.34 0 top
CC300  -  [C_0402]  122.26 85.3 90 bottom
CC301  -  [C_0402]  126.4 86.82 90 bottom
CC302  -  [C_0402]  178.04 86.06 0 bottom
CC310  -  [C_0402]  162.06 63.58 180 top
CC311  -  [C_0402]  165.48 68.6 180 top
CD2  -  [C_0402]  110.27 20.43 270 top
CD3  -  [C_0402]  139.64 20.35 270 top
CD4  -  [C_0402]  130.01 20.4 270 top
CD6  -  [C_0402]  79.87 14.01 90 top
CD7  -  [C_0402]  104.28 20.43 270 top
CD8  -  [C_0402]  112.48 20.4 270 top
CD9  -  [C_0402]  114.77 20.4 270 top
CD10  -  [C_0402]  119.72 20.4 270 top
CD11  -  [C_0402]  116.95 20.5 270 top
CD12  -  [C_0603]  120.86 20.78 270 top
CD13  -  [C_0603]  113.63 20.78 270 top
CD14  -  [C_0603]  111.34 20.78 270 top
CD15  -  [C_0603]  103.14 20.68 270 top
CD16  -  [C_0603]  131.15 20.78 270 top
CD17  -  [C_0603]  138.19 20.87 270 top
CD18  -  [C_0603]  118.18 20.92 270 top
CD19  -  [C_0603]  122.13 20.78 270 top
CD20  -  [C_D3]  115.56 31.83 180 top
CD24  -  [C_0402]  144.34 13 90 top
CD25  -  [C_0402]  142.76 12.73 90 top
CD26  -  [C_0402]  145.12 12.18 270 top
CD27  -  [C_0402]  142.79 11.65 270 top
CD28  -  [C_0603]  140.84 12.55 180 top
CD29  -  [C_0603]  140.84 11.33 180 top
CD30  -  [C_0201]  77.47 10.75 180 top
CD31  -  [C_0402]  143.06 22.79 90 top
CD32  -  [C_0201]  142.17 22.79 90 top
CD35  -  [C_0402]  170.75 11.36 180 top
CD36  -  [C_0402]  122.92 12.22 270 top
CD37  -  [C_0402]  212.3 20.53 270 top
CD38  -  [C_0402]  223.23 20.54 270 top
CD39  -  [C_0402]  203.17 20.54 270 top
CD40  -  [C_0402]  200.62 20.4 270 top
CD41  -  [C_0402]  192.87 20.53 270 top
CD42  -  [C_0402]  190.59 20.53 270 top
CD43  -  [C_0402]  168.87 20.4 270 top
CD44  -  [C_0402]  188.3 20.53 270 top
CD45  -  [C_0603]  194.07 20.95 270 top
CD46  -  [C_0603]  191.73 20.78 270 top
CD47  -  [C_0603]  201.84 21.02 270 top
CD48  -  [C_0603]  204.61 20.81 270 top
CD49  -  [C_0603]  211.16 20.78 270 top
CD50  -  [C_0603]  205.88 20.81 270 top
CD51  -  [C_0603]  189.44 20.78 270 top
CD52  -  [C_0603]  176.36 20.91 270 top
CD53  -  [C_D3]  176.47 30.81 0 top
CD54  -  [C_0402]  73.34 13.92 270 top
CD57  -  [C_0402]  226.4 11.05 180 top
CD58  -  [C_0402]  226.4 12.83 180 top
CD59  -  [C_0402]  226.4 11.94 180 top
CD60  -  [C_0402]  226.4 13.72 180 top
CD61  -  [C_0603]  226.47 15.07 180 top
CD62  -  [C_0603]  226.47 16.34 180 top
CD63  -  [C_0402]  230.47 17.15 90 top
CD64  -  [C_0201]  229.7 17.19 90 top
CD70  -  [C_0402]  146.8 17.86 0 top
CD71  -  [C_0402]  146.8 17 0 top
CD72  -  [C_0603]  147.34 19.37 90 top
CD73  -  [C_0603]  145.25 15.03 180 top
CD74  -  [C_0402]  227.11 18.37 180 top
CD75  -  [C_0402]  227.11 19.26 180 top
CD76  -  [C_0603]  228.18 19.57 90 top
CD77  -  [C_0603]  229.45 19.57 90 top
CD78  -  [C_0402]  101.81 11.33 90 top
CD79  -  [C_0402]  81.6 11.21 90 top
CD80  -  [C_0402]  102.7 11.38 90 top
CD81  -  [C_0402]  114.51 11.38 90 top
CD82  -  [C_0402]  118.63 11.46 90 top
CD83  -  [C_0402]  109.94 11.38 90 top
CD84  -  [C_0402]  106.13 11.26 90 top
CD85  -  [C_0402]  92.54 11.26 90 top
CD86  -  [C_0603]  103.85 10.88 90 top
CD87  -  [C_0603]  107.28 11.13 90 top
CD88  -  [C_0603]  108.55 11.13 90 top
CD89  -  [C_0603]  111.09 11.13 90 top
CD90  -  [C_0603]  113.37 11 90 top
CD91  -  [C_0603]  135.72 11.26 90 top
CD92  -  [C_0603]  117.36 11.33 90 top
CD93  -  [C_0603]  93.69 10.88 90 top
CD94  -  [C_0603]  191.1 11.13 90 top
CD95  -  [C_0603]  185.13 11.26 90 top
CD96  -  [C_0603]  193.51 11.26 90 top
CD97  -  [C_0603]  188.81 11.13 90 top
CD98  -  [C_0603]  174.71 11.26 90 top
CD99  -  [C_0603]  200.37 11.13 90 top
CD100  -  [C_0603]  202.02 11.13 90 top
CD101  -  [C_0603]  203.54 11.13 90 top
CD102  -  [C_0402]  217.77 11.26 90 top
CD103  -  [C_0402]  196.43 11.38 180 top
CD104  -  [C_0402]  192.24 11.38 90 top
CD105  -  [C_0402]  189.95 11.38 90 top
CD106  -  [C_0402]  173.57 11.26 90 top
CD107  -  [C_0402]  187.69 11.46 90 top
CD108  -  [C_0402]  183.98 11.26 90 top
CD109  -  [C_0402]  163.74 11.15 180 top
CE1  -  [C_0603]  247.07 94.8 180 top
CE2  -  [C_0201]  245.07 89.41 90 top
CE3  -  [C_0201]  251.67 87.2 90 bottom
CE4  -  [C_0201]  251.04 75.98 270 top
CE5  -  [C_0201]  256.37 80.67 270 top
CE6  -  [C_0201]  242.2 80.52 180 top
CE7  -  [C_0603]  254.98 73.42 270 top
CE8  -  [C_0402]  256.81 76.43 270 top
CE9  -  [C_0402]  240.32 81.23 180 top
CE10  -  [C_0402]  279.33 50.91 90 top
CE11  -  [C_0201]  272.35 54.42 270 top
CE12  -  [C_0402]  277.46 52.79 0 top
CE13  -  [C_0201]  266.94 68.75 90 top
CE14  -  [C_0402]  264.25 68.71 90 top
CE15  -  [C_0402]  265.6 53.32 0 top
CE16  -  [C_0201]  263.61 54.31 270 top
CE17  -  [C_0201]  274.12 59.88 0 top
CE18  -  [C_0201]  273.26 62.56 0 top
CE19  -  [C_0201]  258.16 66.27 180 top
CE20  -  [C_0201]  265.77 54.06 0 top
CE21  -  [C_0603]  260.59 48.33 90 top
CE22  -  [C_0201]  258.06 61.7 180 top
CE23  -  [C_0201]  265.01 68.66 90 top
CE24  -  [C_0402]  273.65 64.72 270 top
CE25  -  [C_0201]  260.66 54.37 270 top
CE26  -  [C_0402]  272.78 66.3 270 top
CE27  -  [C_0402]  270.6 68.84 90 top
CE28  -  [C_0402]  267.37 52.73 90 top
CE29  -  [C_0402]  269.4 52.78 180 top
CE30  -  [C_0402]  258.07 59.19 180 top
CE31  -  [C_0603]  272.76 67.52 0 top
CE32  -  [C_0603]  69.81 70.54 35.9 bottom
CE34  -  [C_0402]  262.09 71.25 90 top
CE35  -  [C_0402]  142.81 63.15 270 top
CE36  -  [C_0402]  134.1 90.53 270 bottom
CE37  -  [C_0402]  254.29 13.57 0 top
CE38  -  [C_0402]  269.4 69.68 180 top
CE39  -  [C_0402]  98.71 70.16 270 top
CE40  -  [C_0402]  275.3 63.17 90 top
CE44  -  [C_0402]  272.02 51.72 180 top
CE45  -  [C_0402]  271.49 54.31 270 top
CE46  -  [C_0402]  151.64 25.46 270 bottom
CE47  -  [C_0402]  275.3 65.49 90 top
CE52  -  [C_0402]  254.93 68.16 90 top
CE53  -  [C_0402]  225.15 75.25 180 top
CI1  -  [C_1206]  19.3 92.18 0 bottom
CI3  -  [C_0201]  20.14 93.45 0 bottom
CI4  -  [C_0402]  21.68 76.48 270 bottom
CI5  -  [C_0402]  20.79 76.48 270 bottom
CI6  -  [C_0603]  19.76 86.92 0 bottom
CI7  -  [C_0201]  18.79 86.95 180 bottom
CI8  -  [C_1206]  75.25 103.67 90 top
CI10  -  [C_0201]  71.84 95.46 180 top
CI11  -  [C_0603]  72.1 88.09 180 top
CI12  -  [C_0201]  71.84 88.98 180 top
CI13  -  [C_0402]  284.74 59.24 180 top
CI14  -  [C_1206]  286.9 59.86 90 bottom
CI16  -  [C_0402]  284.74 58.35 180 top
CI17  -  [C_0201]  284.92 58.75 180 bottom
CI19  -  [C_0201]  281.98 61.2 90 bottom
CI27  -  [C_0402]  67.22 91.14 270 top
CI28  -  [C_0402]  68.11 91.14 270 top
CI29  -  [C_0402]  235.93 71.84 90 top
CI30  -  [C_0402]  236.82 71.84 90 top
CI31  -  [C_0402]  281.25 60.76 90 bottom
CI32  -  [C_B2-NPM]  286.9 59.86 270 bottom
CI33  -  [C_0402]  279.19 65.22 180 top
CI34  -  [C_0402]  23.46 88.59 180 top
CI35  -  [C_0402]  73.83 91.28 270 top
CL1  -  [C_0402]  264.25 94.4 90 top
CL2  -  [C_0402]  263.38 94.42 90 top
CL3  -  [C_0201]  261.16 85.81 0 bottom
CL4  -  [C_0603]  261.41 92.52 90 bottom
CL5  -  [C_0402]  262.52 95.33 270 top
CL6  -  [C_0402]  261.66 95.33 270 top
CL7  -  [C_0201]  261.14 87.71 0 bottom
CL8  -  [C_0201]  261.2 85.17 0 bottom
CL9  -  [C_0201]  266.37 82.5 0 top
CL10  -  [C_0201]  262.5 92.73 90 bottom
CL11  -  [C_0201]  263.1 82.41 270 top
CL12  -  [C_0603]  260.34 92.5 90 top
CL13  -  [C_0402]  256.88 84.48 270 top
CL14  -  [C_0402]  259.55 83.57 90 top
CL15  -  [C_0201]  273.55 84.42 0 top
CL16  -  [C_0201]  281.83 82.59 270 bottom
CL17  -  [C_0201]  282.43 82.59 270 bottom
CL18  -  [C_0402]  288.15 92.21 270 bottom
CL19  -  [C_0201]  261 95.42 270 bottom
CL20  -  [C_0201]  271.85 84.04 270 top
CL21  -  [C_0201]  271.29 84.04 270 top
CL22  -  [C_1808]  284.01 87.33 90 bottom
CL25  -  [C_0201]  270.98 79.04 90 top
CL26  -  [C_0201]  272.17 76.23 270 top
CL27  -  [C_0201]  275.78 72.75 270 top
CL28  -  [C_0805]  256.63 88.26 90 bottom
CMOS1  -  [SHORTPADS-NPM]  262.04 26.23 90 bottom
CN1  -  [C_0603]  257.26 35.46 90 top
CN2  -  [C_0201]  258.15 35.4 90 top
CN13  -  [C_0402]  278.52 17.56 0 top
CN14  -  [C_0201]  278.56 16.8 0 top
CN15  -  [C_0201]  275.13 17.99 0 top
CN16  -  [C_0201]  275.13 17.35 0 top
CN17  -  [C_0402]  266.69 23.13 180 top
CN18  -  [C_0402]  266.69 24.14 180 top
CN19  -  [C_0201]  225.31 27.24 180 top
CN20  -  [C_0402]  233.01 31.75 90 top
CN21  -  [C_0402]  230.82 35.19 270 top
CN22  -  [C_0402]  229.93 35.19 270 top
CN23  -  [C_0402]  228.15 35.19 270 top
CN24  -  [C_0402]  229.04 35.19 270 top
CN25  -  [C_0402]  231.45 25.13 90 top
CN26  -  [C_0402]  230.56 25.13 90 top
CN29  -  [C_0201]  243.42 33.48 90 top
CN30  -  [C_0402]  237.12 26.35 180 top
CN31  -  [C_0402]  241.49 34.05 270 top
CN32  -  [C_0402]  242.37 34.05 270 top
CN33  -  [C_0402]  239.58 34.05 270 top
CN34  -  [C_0402]  240.47 34.05 270 top
CN35  -  [C_0402]  243.64 24.11 90 top
CN36  -  [C_0402]  242.76 24.11 90 top
CN41  -  [C_0201]  275.13 12.53 0 top
CN42  -  [C_0201]  275.13 11.51 0 top
CN43  -  [C_0402]  266.69 25.92 180 top
CN44  -  [C_0402]  266.69 25.03 180 top
CN45  -  [C_0402]  257.22 22.92 0 top
CN46  -  [C_0402]  265.82 22.18 0 top
CN47  -  [C_0402]  257.22 24.7 0 top
CN48  -  [C_0402]  257.22 22.03 0 top
CN49  -  [C_0201]  258.13 26.98 180 top
CN50  -  [C_0402]  257.22 23.81 0 top
CR8  -  [C_0201]  266.53 40.85 270 top
CR9  -  [C_0603]  258.29 39.75 180 top
CR10  -  [C_0201]  257.89 40.64 180 top
CR13  -  [C_0201]  259.29 43.9 90 top
CR23  -  [C_0402]  258.91 35.94 90 top
CR24  -  [C_0402]  263.44 46.33 270 top
CR25  -  [C_0402]  262.55 46.33 270 top
CR26  -  [C_0402]  261.2 46.36 270 top
CR27  -  [C_0402]  260.31 46.36 270 top
CR35  -  [C_0402]  264.88 37.93 270 top
CR36  -  [C_0201]  257.81 42.12 180 top
CR37  -  [C_0402]  260.69 37.88 270 top
CR38  -  [C_0603]  271.07 38.6 270 top
CR39  -  [C_0201]  269.54 34.48 0 top
CR40  -  [C_0603]  304.13 22.53 180 top
CR41  -  [C_0201]  303.77 21.62 180 top
CR42  -  [C_0402]  267.3 40.72 0 top
CR43  -  [C_0402]  258.1 41.36 180 top
CV1  -  [C_0402]  81.88 83.06 90 bottom
CV2  -  [C_0402]  80.99 83.06 90 bottom
CV3  -  [C_0402]  80.1 83.06 90 bottom
CV4  -  [C_0402]  79.21 83.06 90 bottom
CV5  -  [C_0402]  78.32 83.06 90 bottom
CV6  -  [C_0402]  77.43 83.06 90 bottom
CV7  -  [C_0603]  89.14 85.92 90 top
CV8  -  [C_0201]  84.29 87.68 90 top
CV9  -  [C_0603]  97.07 84.32 0 bottom
CV10  -  [C_0402]  93.37 79.99 90 bottom
CV11  -  [C_0402]  88.89 80.04 0 bottom
CV12  -  [C_0603]  90.41 85.92 90 top
CV13  -  [C_0402]  86.91 94.44 270 top
CV14  -  [C_0402]  87.77 94.44 270 top
CV17  -  [C_0402]  81.32 94.8 270 top
CV18  -  [C_0402]  82.18 94.8 270 top
CV21  -  [C_0402]  84.16 93.88 270 top
CV22  -  [C_0402]  85.03 93.88 270 top
CV23  -  [C_0201]  75.37 92.55 270 top
CV26  -  [C_0201]  91.23 99 270 top
CV27  -  [C_0603]  92.11 98.9 270 top
CV28  -  [C_0402]  89.65 93.86 270 top
CV29  -  [C_0402]  90.51 93.86 270 top
CV50  -  [C_0402]  240.9 103.18 0 bottom
CV51  -  [C_0402]  232.8 95.56 180 bottom
CV52  -  [C_0402]  234.3 95.56 0 bottom
CV53  -  [C_0402]  236.71 95.44 0 bottom
CV54  -  [C_0402]  231.88 97.6 0 bottom
CV55  -  [C_0402]  235.21 97.6 180 bottom
CV56  -  [C_0402]  237.67 97.49 180 bottom
CV57  -  [C_0402]  245.37 103.18 180 bottom
CV58  -  [C_0402]  242.68 103.18 0 bottom
CV59  -  [C_0402]  240.07 103.19 180 bottom
CV79  -  [C_0402]  201.89 86.54 180 bottom
CV80  -  [C_0402]  201.89 85.65 180 bottom
CV82  -  [C_0603]  217.87 81.98 270 bottom
CV83  -  [C_0201]  217.41 92.75 90 bottom
CV84  -  [C_0201]  217.38 90.08 90 bottom
CV85  -  [C_0402]  215.81 84.79 180 bottom
CV86  -  [C_0402]  214.08 90.45 270 bottom
CV87  -  [C_0603]  216.6 81.98 270 bottom
CV88  -  [C_0201]  215.64 85.55 180 bottom
CV89  -  [C_0402]  213.19 90.45 270 bottom
CV90  -  [C_0603]  219.54 83.65 0 bottom
CV91  -  [C_0201]  216.11 92.75 90 bottom
CV92  -  [C_0402]  214.08 88.55 270 bottom
CV93  -  [C_0402]  219.72 84.79 0 bottom
CV94  -  [C_0603]  220.5 93.55 180 bottom
CV95  -  [C_0201]  214.34 92.62 90 bottom
CV96  -  [C_0402]  214.08 86.77 270 bottom
CV97  -  [C_0402]  220.86 86.69 0 bottom
CV98  -  [C_0402]  218.15 92.71 90 bottom
CV99  -  [C_0402]  220.38 89.49 180 bottom
CV100  -  [C_0201]  214.25 91.52 180 bottom
CV101  -  [C_0603]  221.58 89.55 270 bottom
CV102  -  [C_0402]  218.83 81.66 90 top
CV103  -  [C_0402]  219.72 81.66 90 top
CV104  -  [C_0402]  217.08 81.66 90 top
CV105  -  [C_0402]  217.97 81.66 90 top
CV106  -  [C_0402]  215.33 81.66 90 top
CV107  -  [C_0402]  216.22 81.66 90 top
CV108  -  [C_0402]  213.6 81.66 90 top
CV109  -  [C_0402]  214.46 81.66 90 top
CV110  -  [C_0402]  220.61 81.66 90 top
CV111  -  [C_0402]  221.5 81.66 90 top
CV113  -  [C_0402]  224.19 84.2 90 top
CV114  -  [C_0201]  207.05 89.21 0 bottom
CV115  -  [C_0402]  224.2 83.34 270 top
CV118  -  [C_0201]  127.38 89.64 180 bottom
CV119  -  [C_0402]  118.81 93.58 90 bottom
CV120  -  [C_0402]  119.67 93.58 90 bottom
CV121  -  [C_0201]  147.9 92.21 0 bottom
CV122  -  [C_0402]  148.04 83.21 180 bottom
CV123  -  [C_0402]  144.13 83.21 0 bottom
CV124  -  [C_0201]  230.21 92.26 180 top
CV125  -  [C_0201]  230.26 90.99 180 top
CV126  -  [C_0201]  235.4 94.83 90 top
CV127  -  [C_0402]  233.87 88.24 270 top
CV128  -  [C_0402]  230.26 93.6 180 top
CV144  -  [C_0201]  240.12 93.04 0 top
CV145  -  [C_0402]  247.68 15.43 270 top
CV146  -  [C_0402]  248.57 15.43 270 top
CV147  -  [C_0402]  250.48 15.43 270 top
CV148  -  [C_0402]  249.59 15.43 270 top
CV149  -  [C_0402]  248.5 23 270 top
CV150  -  [C_0402]  247.61 23 270 top
CV152  -  [C_0402]  249.39 23 270 top
CV153  -  [C_0402]  250.27 23 270 top
CV156  -  [C_0402]  251.16 23 270 top
CV157  -  [C_0402]  252.05 23 270 top
CV374  -  [C_0402]  90.66 80.09 270 bottom
CV600  -  [C_0201]  198.64 81.92 180 top
CV601  -  [C_0201]  189.83 83.99 90 top
CV602  -  [C_0201]  187.79 86.91 90 top
CV603  -  [C_0402]  201.59 88.01 0 top
CV604  -  [C_0402]  189.7 90.43 90 bottom
CV605  -  [C_0402]  198.97 90.41 90 bottom
CV606  -  [C_0402]  190.76 91.38 270 bottom
CV607  -  [C_0402]  191.65 91.38 270 bottom
CV608  -  [C_0402]  193.56 91.32 270 bottom
CV609  -  [C_0402]  194.45 91.32 270 bottom
CV610  -  [C_0402]  195.34 91.32 270 bottom
CV611  -  [C_0402]  196.23 91.32 270 bottom
CV612  -  [C_0402]  197.12 91.32 270 bottom
CV613  -  [C_0402]  198 91.32 270 bottom
CV615  -  [C_0201]  227.73 90.74 0 bottom
CV616  -  [C_0402]  226.02 94.21 180 bottom
CV617  -  [C_0603]  232.12 99.27 180 top
CV618  -  [C_0603]  227.26 97.29 180 top
CV619  -  [C_0402]  228.07 94.55 270 top
CZ1  -  [C_0201]  91.32 86.35 270 top
CZ2  -  [C_0201]  99.02 85.97 270 top
CZ10  -  [C_0201]  262.19 11.37 90 top
CZ11  -  [C_0201]  262.78 11.37 90 top
CZ12  -  [C_0201]  265.43 11.64 180 top
CZ13  -  [C_0402]  252.13 15.4 270 top
CZ14  -  [C_0402]  253.05 15.4 270 top
CZ15  -  [C_0201]  244.05 21.89 90 top
CZ16  -  [C_0402]  260.24 20.56 270 top
CZ17  -  [C_0201]  259.52 20.44 270 top
CZ18  -  [C_0201]  243.42 21.89 90 top
CZ19  -  [C_0603]  261.33 20.49 270 top
CZ20  -  [C_0402]  244.82 21.97 90 top
CZ21  -  [C_0402]  261.83 16.08 270 top
CZ22  -  [C_0402]  260.95 16.08 270 top
CZ23  -  [C_0402]  247.74 52.84 90 top
CZ24  -  [C_0201]  264.25 11.55 90 top
CZ27  -  [C_0201]  221.93 36.11 180 top
CZ28  -  [C_0201]  217.3 38.75 270 top
CZ29  -  [C_0201]  202.47 35.48 270 top
CZ30  -  [C_0402]  219.37 36.78 0 top
CZ31  -  [C_0402]  218.44 34.38 180 top
CZ34  -  [C_0201]  217.78 28.68 90 top
CZ36  -  [C_0201]  247.86 37.76 90 top
CZ37  -  [C_0402]  250.35 35.77 180 top
CZ38  -  [C_0402]  246.85 52.84 90 top
CZ39  -  [C_0201]  245.71 50.96 270 top
CZ42  -  [C_0402]  247.94 41.58 0 top
CZ43  -  [C_0201]  250.91 44.15 90 top
CZ44  -  [C_0201]  242.37 44.4 0 top
CZ45  -  [C_0402]  240.58 45.8 180 top
CZ46  -  [C_0402]  251.29 35.77 0 top
CZ47  -  [C_0201]  252.06 38.82 90 top
CZ48  -  [C_0201]  288.76 62.69 180 top
CZ50  -  [C_0201]  250.02 50.92 270 top
CZ51  -  [C_0402]  241.06 77.07 0 top
CZ52  -  [C_0402]  241.03 77.98 0 top
CZ53  -  [C_0402]  242.76 61.27 0 top
CZ54  -  [C_0603]  242.33 58.08 0 top
CZ55  -  [C_0402]  242.76 60.26 0 top
CZ57  -  [C_B2]  237.96 83.27 0 bottom
CZ58  -  [C_0402]  234.48 66.12 180 top
CZ59  -  [C_0402]  234.48 65.23 180 top
CZ60  -  [C_0603]  270.92 11.13 180 top
CZ61  -  [C_0603]  270.92 12.4 180 top
CZ64  -  [C_0201]  240.41 47.83 180 top
CZ65  -  [C_0402]  285.42 81.71 180 bottom
CZ66  -  [C_0402]  285.42 80.57 180 bottom
CZ67  -  [C_0402]  285.42 82.72 180 bottom
CZ68  -  [C_0402]  261.45 11.43 90 top
CZ69  -  [C_0402]  240.58 46.94 180 top
CZ71  -  [C_0201]  186.81 63.4 270 top
CZ72  -  [C_0603]  187.7 62.89 270 top
CZ73  -  [C_0201]  191.25 62.5 0 top
CZ74  -  [C_0201]  193.92 68.37 0 top
CZ75  -  [C_0201]  187.32 71.96 180 top
CZ76  -  [C_0603]  193.93 69.27 0 top
CZ77  -  [C_0402]  190.13 76.15 0 top
CZ78  -  [C_0201]  164.46 84.12 270 bottom
CZ82  -  [C_0201]  163.79 91.72 270 bottom
CZ84  -  [C_0402]  168.92 84.61 180 bottom
CZ85  -  [C_0201]  174.93 85.04 0 bottom
CZ87  -  [C_0402]  168.87 93.35 90 bottom
CZ89  -  [C_0201]  273.73 49.04 90 top
CZ90  -  [C_0402]  274.49 49.17 90 top
CZ91  -  [C_0402]  275.95 48.54 90 top
CZ92  -  [C_0201]  276.95 48.59 90 top
CZ94  -  [C_0201]  263.34 13 0 top
CZ95  -  [C_0402]  164.07 88.57 180 bottom
CZ99  -  [C_0201]  266.66 30.52 90 top
CZ100  -  [C_0402]  264.83 28.27 180 top
CZ105  -  [C_0402]  242.71 59.39 0 top
CZ106  -  [C_0402]  245.71 21.97 90 top
CZ113  -  [C_0402]  156.99 44.01 0 top
CZ114  -  [C_0201]  160.72 42.01 0 top
CZ115  -  [C_0201]  187.45 33.21 270 top
D19  -  [RB751S40T1G_SOD523-2]  179.6 95.76 0 bottom
D20  -  [L30ESD24VC3-2_SOT23-3]  134.38 92.97 180 bottom
DA1  -  [L03ESDL5V0CC3-2_SOT23-3]  295.85 38.03 90 top
DA2  -  [L03ESDL5V0CC3-2_SOT23-3]  296.4 25.23 90 top
DA3  -  [L03ESDL5V0CC3-2_SOT23-3]  296.38 31.83 90 top
DA4  -  [RB751S40T1G_SOD523-2]  280 25.42 270 top
DA5  -  [RB751S40T1G_SOD523-2]  283.04 25.29 270 top
DA6  -  [L03ESDL5V0CC3-2_SOT23-3]  284.44 14.46 0 bottom
DA7  -  [L03ESDL5V0CC3-2_SOT23-3]  288.5 14.46 0 bottom
DE1  -  [RB751S40T1G_SOD523-2]  69.07 71.5 36 bottom
DI1  -  [L05ESDL5V0NA-4_SLP2510P8-10-9]  19.41 80.53 180 bottom
DI2  -  [AZC199-02SPR7G_SOT23-3]  18.99 84.28 90 bottom
DI3  -  [AZC199-02SPR7G_SOT23-3]  71.77 90.66 0 bottom
DI4  -  [L05ESDL5V0NA-4_SLP2510P8-10-9]  288.02 60.53 90 top
DI5  -  [AZC199-02SPR7G_SOT23-3]  283.31 62.41 180 bottom
DI6  -  [L05ESDL5V0NA-4_SLP2510P8-10-9]  65.75 94.19 180 top
DV1  -  [BAT54CW_SOT323-3]  87.01 84.37 180 bottom
DV2  -  [BAT54CW_SOT323-3]  84.47 84.36 180 bottom
DV3  -  [BAT54CW_SOT323-3]  98.96 80.1 180 bottom
DV4  -  [AZC199-02SPR7G_SOT23-3]  111.72 89.97 270 bottom
DV5  -  [PJDLC05C_SOT23-3]  233.87 99.35 180 bottom
DV6  -  [PJDLC05C_SOT23-3]  238.06 99.35 180 bottom
DZ1  -  [RB751S40T1G_SOD523-2]  254.72 24.72 90 top
DZ2  -  [RB751S40T1G_SOD523-2]  255.87 24.72 90 top
DZ3  -  [RB751S40T1G_SOD523-2]  286.06 67.19 90 bottom
DZ4  -  [RB751S40T1G_SOD523-2]  282.74 71.7 270 bottom
DZ5  -  [RB751S40T1G_SOD523-2]  240.75 73.8 90 top
DZ6  -  [RB751S40T1G_SOD523-2]  240.98 71.69 0 top
DZ7  -  [RB751S40T1G_SOD523-2]  256.66 14.27 0 top
FD1  -  [FIDUCIAL_C40M80]  252.03 102.04 180 bottom
FD2  -  [FIDUCIAL_C40M80]  64.58 12.02 180 bottom
FD3  -  [FIDUCIAL_C40M80]  50.91 13.95 0 top
FD4  -  [FIDUCIAL_C40M80]  296.48 86.01 0 top
H1  -  [H_3P8]  122.9 79.5 0 top
H2  -  [H_3P8]  183.6 79.5 0 top
H3  -  [H_3P8]  122.9 52.2 0 top
H4  -  [H_3P8]  183.6 52.2 0 top
H5  -  [H_2P6N]  291.1 5.35 0 top
H6  -  [H_3P0X2P0N]  15.25 97.85 0 top
H7  -  [H_3P2]  279.42 68.3 0 top
H8  -  [H_3P2]  252.95 48.35 0 top
H9  -  [H_0P9N]  300.85 88.27 0 top
H10  -  [H_0P8N]  287.8 79.06 0 top
H11  -  [H_2P4]  10 97.85 0 top
H12  -  [H_2P4]  153.25 11.4 0 top
H13  -  [H_2P4]  52.25 106.35 0 top
H14  -  [H_2P4]  120.25 106.75 0 top
H15  -  [H_2P4]  153.25 19.35 0 top
H16  -  [H_2P4]  137.25 85.7 0 top
H17  -  [H_2P4]  45.5 12.05 0 top
H18  -  [H_2P4]  186.25 105.35 0 top
H19  -  [H_2P4]  223.25 108.95 0 top
H20  -  [H_2P4]  253.74 108.96 0 top
H21  -  [H_2P4]  285.25 53.85 0 top
H22  -  [H_2P4]  231.25 54.35 0 top
H23  -  [H_3P3]  104 88.4 0 top
H24  -  [H_2P4]  295.25 3.35 0 top
H25  -  [H_3P8]  238.35 11.85 0 top
JAPS1  -  [ACES_50506-01841-P01_18P-NPM]  299.51 25.95 90 top
JCRT1  -  [FUTUR_061-D531-0207_15P]  235.01 107.15 0 bottom
JDEG1  -  [HB_A531015-SCHR21_10P]  299.51 40.3 90 top
JDIMM1  -  [LOTES_ADDR0107-P005A_260P-T]  78.87 19.95 180 bottom
JDIMM2  -  [LOTES_ADDR0107-P005A_260P-T]  160.87 19.95 180 bottom
JDOCK1  -  [JAE_WD2F144WB5R400_144P]  134.5 100.75 0 bottom
JEDP1  -  [ACES_50398-04041-001_40P]  97.25 86.45 180 bottom
JFAN1  -  [ACES_50271-0040N-001_4P]  65.27 71.73 135 bottom
JHDMI1  -  [CONCR_099BKAC19YBLCNF_19P]  82.1 103.7 0 bottom
JHP1  -  [SINGA_2SJ3095-022111F_6P-T]  293.5 18.85 90 bottom
JIR1  -  [ACES_50450-0067N-P01_6P]  229.8 62.36 90 bottom
JKBTP1  -  [ACES_50506-02041-P01_20P]  204.8 33.75 0 top
JLED1  -  [ACES_50506-00841-P01_8P]  278.65 8.95 0 top
JLOM1  -  [SANTA_130456-511_13P-T]  271.43 101.07 0 bottom
JLPDE1  -  [HB_A531015-SCHR21_10P]  246.8 66.75 0 top
JNGFF1  -  [BELLW_80148-4221_67P]  243.7 14.82 0 bottom
JNGFF2  -  [BELLW_80149-4221_67P]  233.89 77.55 270 bottom
JNGFF3  -  [BELLW_SD-80159-4221_67P-T]  266.55 9.2 180 bottom
JRTC1  -  [ACES_50271-0020N-001_2P]  274.29 5.89 180 bottom
JSATA1  -  [STARC_115B20-100020-G2-R_20P]  270.5 17.55 0 bottom
JSD1  -  [T-SOL_156-2000302608_19P_NR]  274.47 41.06 270 bottom
JSIM1  -  [T-SOL_5-991503004000-6_8P-T]  290.48 86.11 270 bottom
JSPI1  -  [E-T_6705K-Y20N-00L_20P]  214.64 45.19 0 top
JSPK1  -  [ACES_50271-0040N-001_4P]  282.7 6 180 bottom
JTAG1  -  [SHORTPADS]  255.1 59.19 0 top
JUART1  -  [ACES_50207-00471-P01_4P-T]  24.17 90.29 90 bottom
JUSB1  -  [LOTES_AUSB0014-P003A_9P]  15.43 88.65 90 bottom
JUSB2  -  [ACON_TARAV-9R1U91_9P]  67.95 99.77 0 bottom
JUSB3  -  [SINGA_2UB4008-900101F_9P]  290.69 56.98 270 bottom
JUSH1  -  [E-T_6705K-Y26N-00L_26P]  259.96 8.7 0 top
JXDP1  -  [SAMTE_BSH-030-01-L-D-A_60P]  79.61 42.62 0 top
LA2  -  [MURAT_BLM15BD601SN1D_2P]  289.12 38.43 0 top
LA3  -  [MURAT_BLM15BD601SN1D_2P]  289.12 36.91 0 top
LA5  -  [MURAT_BLM15PX600SN1D_2P]  286.6 25.35 270 top
LA6  -  [MURAT_BLM15PX330SN1D_2P]  283.93 18.24 270 bottom
LA7  -  [MURAT_BLM15PX330SN1D_2P]  285.46 18.24 270 bottom
LA8  -  [MURAT_BLM15PX330SN1D_2P]  287.36 18.24 270 bottom
LA9  -  [MURAT_BLM15PX330SN1D_2P]  289.01 18.24 270 bottom
LA10  -  [MURAT_BLM15PX330SN1D_2P]  289.15 32.47 0 top
LA11  -  [MURAT_BLM15PX330SN1D_2P]  289.12 35.39 0 top
LC1  -  [MURAT_BLM15PX600SN1D_2P]  161.24 62.3 0 top
LC2  -  [MURAT_BLM15PX600SN1D_2P]  167.17 68.13 180 top
LED3  -  [LED_LTW-C193DC-C_2P]  297 91.25 0 top
LI3  -  [INPAQ_MCM1012B900F06BP_4P]  24.21 84.28 180 bottom
LI4  -  [INPAQ_MCM1012B900F06BP_4P]  73.18 86.11 180 bottom
LI7  -  [INPAQ_MCM1012B900F06BP_4P]  284.06 67.76 270 bottom
LL1  -  [TAIYO_BRC2012T4R7MD_2P]  259.05 86.86 270 bottom
LV1  -  [MURAT_BLM15BB221SN1D_2P]  87.61 86.91 90 top
LV16  -  [MURAT_BLM15BB470SN1D_2P]  232.72 96.58 180 bottom
LV17  -  [MURAT_BLM15BB470SN1D_2P]  234.38 96.58 0 bottom
LV18  -  [MURAT_BLM15BB470SN1D_2P]  236.92 96.45 0 bottom
LV19  -  [MURAT_BLM15AG121SN1D_L0402_2P]  240.71 97.78 90 bottom
LV20  -  [MURAT_BLM15AG121SN1D_L0402_2P]  242.02 98.76 90 bottom
LV22  -  [MURAT_BLM15PX181SN1D_2P]  220.05 81.23 180 bottom
LV23  -  [MURAT_BLM15PX181SN1D_2P]  220.05 82.38 180 bottom
LV24  -  [MURAT_BLM15PX181SN1D_2P]  221.58 92.16 90 bottom
LV25  -  [MURAT_BLM15PX181SN1D_2P]  221.58 90.51 90 bottom
LV27  -  [INPAQ_MCM1012B900F06BP_4P]  113.1 87.74 0 bottom
LZ1  -  [INPAQ_MCM1012B900F06BP_4P]  93.48 82.82 90 bottom
NOREF  -  []  167.48 -48.35 0 top
NOREF#2  -  []  223.25 108.95 0 top
NOREF#3  -  []  153.25 19.35 0 top
NOREF#4  -  []  81.15 159.5 0 top
NOREF#5  -  []  120.25 106.75 0 top
NOREF#6  -  []  45.5 12.05 0 top
NOREF#7  -  []  279.42 68.3 0 top
NOREF#8  -  []  137.25 85.7 0 top
NOREF#9  -  []  122.9 79.5 0 top
NOREF#10  -  []  253.74 108.96 0 top
NOREF#11  -  []  125.56 37.76 0 top
NOREF#12  -  []  163.11 23.83 0 top
NOREF#13  -  []  285.25 53.85 0 top
NOREF#14  -  []  98.75 27.1 90 top
NOREF#15  -  []  295.25 3.35 0 top
NOREF#16  -  []  132.38 26.95 0 top
NOREF#17  -  []  238.35 11.85 0 top
NOREF#18  -  []  183.6 52.2 0 top
NOREF#19  -  []  183.6 79.5 0 top
NOREF#20  -  []  231.25 54.35 0 top
NOREF#21  -  []  108.4 24.15 0 top
NOREF#22  -  []  153.25 11.4 0 top
NOREF#23  -  []  148.8 -12.24 0 top
NOREF#24  -  []  104 88.4 0 top
NOREF#25  -  []  52.25 106.35 0 top
NOREF#26  -  []  252.95 48.35 0 top
NOREF#27  -  []  186.25 105.35 0 top
NOREF#28  -  []  10 97.85 0 top
NOREF#29  -  []  122.9 52.2 0 top
NOREF#30  -  []  185.64 -16.74 0 top
NOREF#31  -  []  123.05 29.54 180 bottom
NOREF#32  -  []  200.02 30.34 180 bottom
NOREF#33  -  []  120.29 -6.59 180 bottom
PBATT1  -  [DEREN_40-42251-01001RHF_10P-T]  66.35 23.79 210 bottom
PC1  -  [C_0603]  45.69 89.35 270 top
PC2  -  [C_0603]  277.5 14.57 0 top
PC3  -  [C_0402]  62.19 21.29 270.2 top
PC4  -  [C_0402]  53.73 14.69 0.4 top
